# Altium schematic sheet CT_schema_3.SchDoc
size 400 x 230 mm
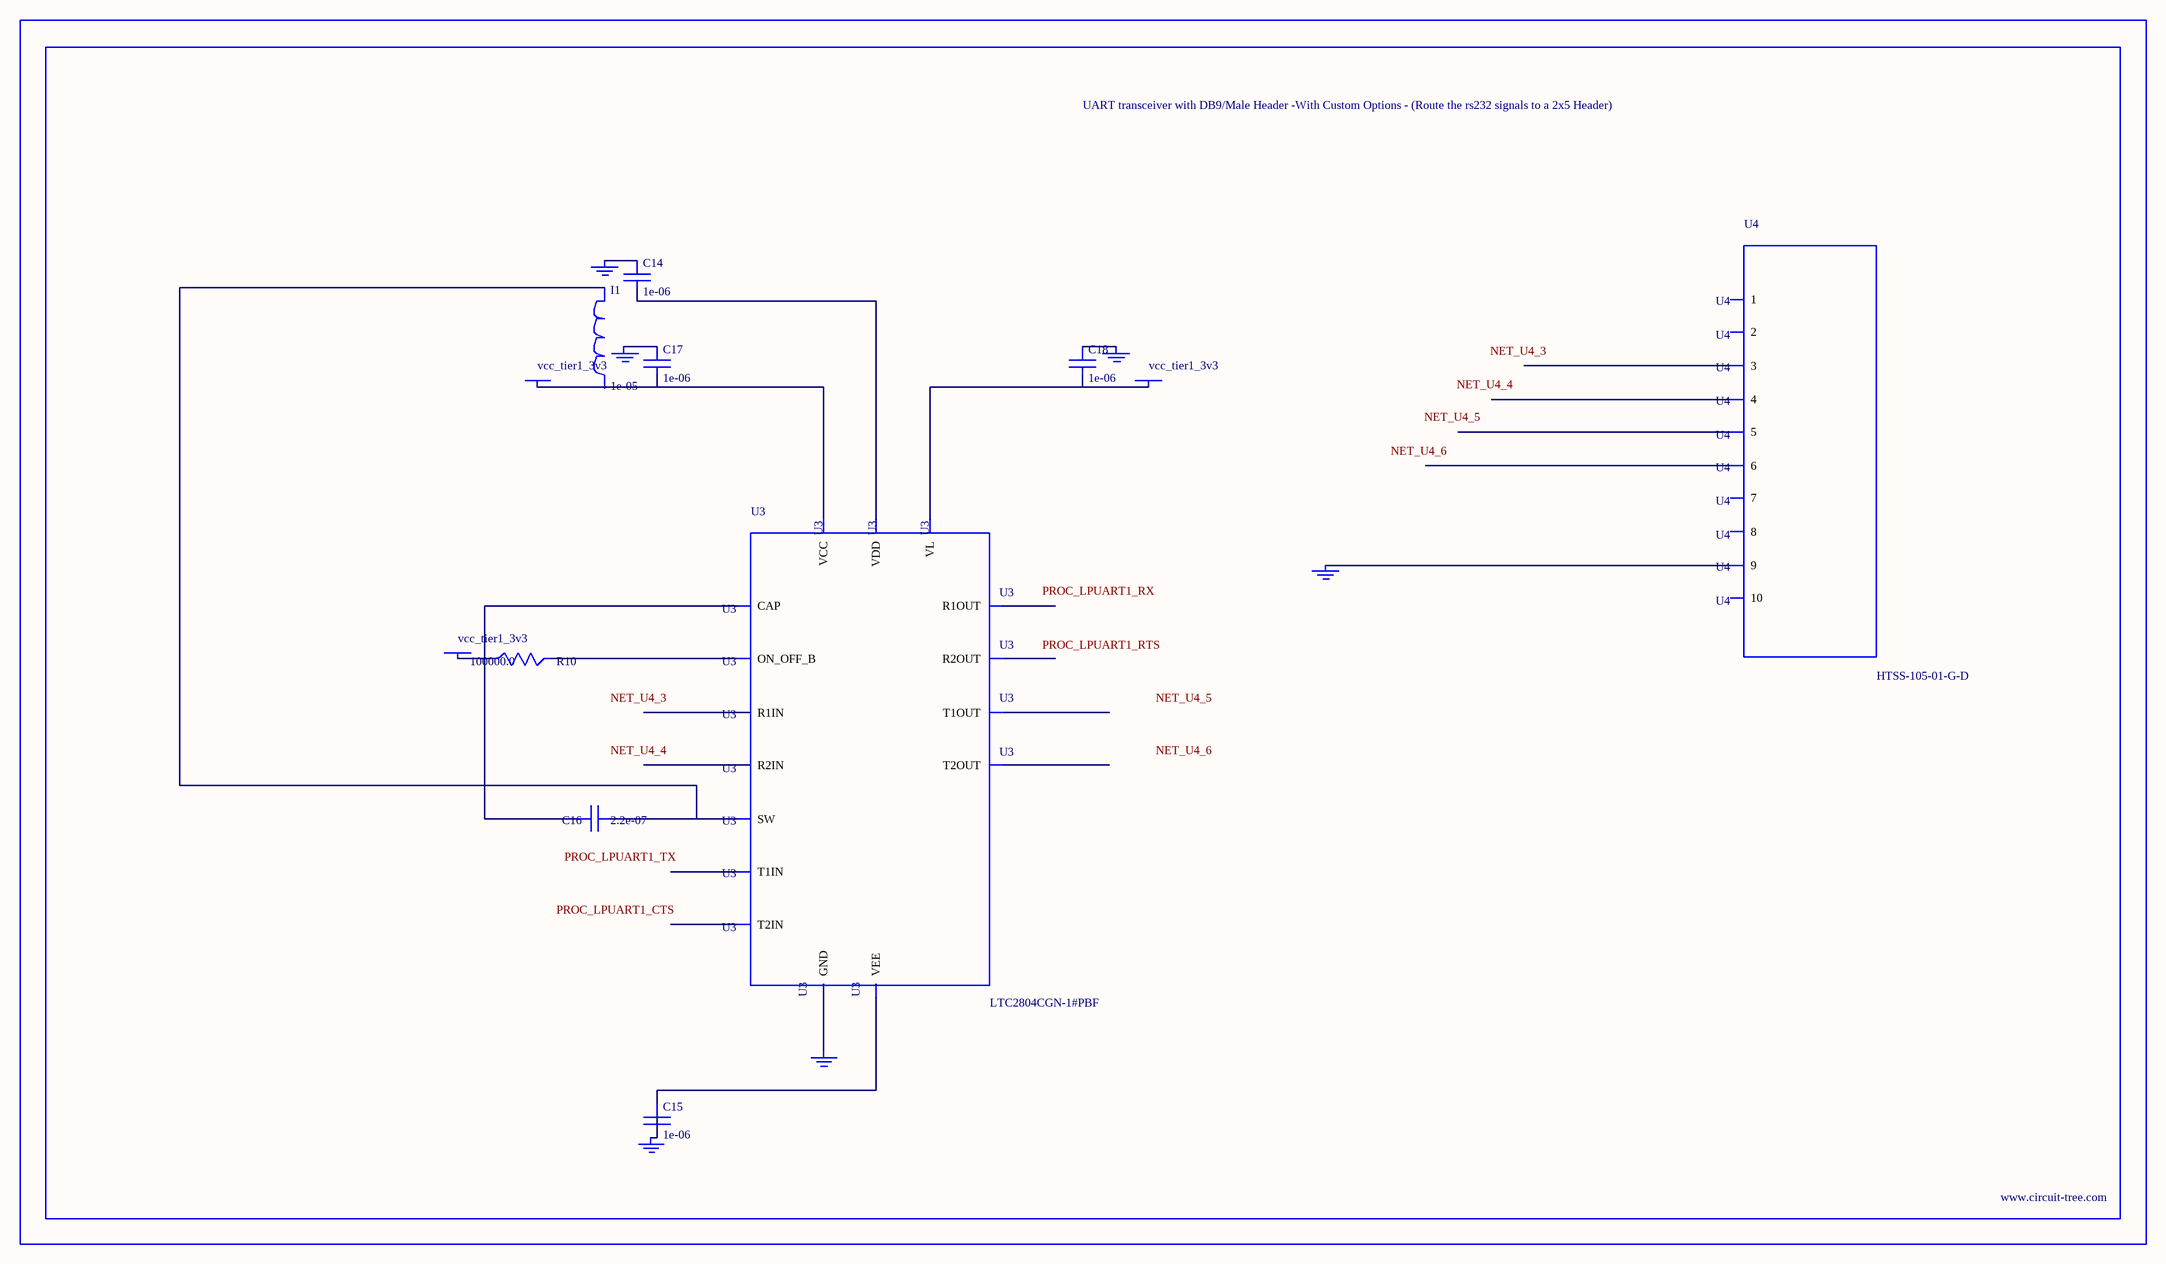
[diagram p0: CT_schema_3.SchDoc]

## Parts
BORDER2  (no value)
C14  1e-06  [C0603]
C15  1e-06  [C0603]
C16  2.2e-07  [C0603]
C17  1e-06  [C0603]
C18  1e-06  [C0603]
GND_INSTANCE_2_0  (no value)
GND_INSTANCE_2_1  (no value)
GND_INSTANCE_2_2  (no value)
GND_INSTANCE_2_3  (no value)
GND_INSTANCE_2_4  (no value)
GND_INSTANCE_2_5  (no value)
I1  1e-05  [L1210]
POWER_INSTANCE_2_0  vcc_tier1_3v3
POWER_INSTANCE_2_1  vcc_tier1_3v3
POWER_INSTANCE_2_2  vcc_tier1_3v3
R10  100000.0  [R0603]
U3  LTC2804CGN-1#PBF  [SSOP-16]
U4  HTSS-105-01-G-D  [HTSS-105-01-G-D]

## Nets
NetC14_1: C14.1 GND_INSTANCE_2_1.0(GND)
NetC14_2: C14.2 U3.6(VDD)
NetC15_1: C15.1 U3.9(VEE)
NetC15_2: C15.2 GND_INSTANCE_2_2.0(GND)
NetC16_1: C16.1 I1.1 U3.7(SW)
NetC16_2: C16.2 U3.10(CAP)
NetC17_1: C17.1 GND_INSTANCE_2_0.0(GND)
NetC17_2: C17.2 POWER_INSTANCE_2_0.0(PWR) U3.5(VCC)
NetC18_1: C18.1 GND_INSTANCE_2_3.0(GND)
NetC18_2: C18.2 POWER_INSTANCE_2_2.0(PWR) U3.12(VL)
NetGND_INSTANCE_2_4_0: GND_INSTANCE_2_4.0(GND) U3.8(GND)
NetGND_INSTANCE_2_5_0: GND_INSTANCE_2_5.0(GND) U4.9
NetPOWER_INSTANCE_2_1_0: POWER_INSTANCE_2_1.0(PWR) R10.1
NetR10_2: R10.2 U3.11(ON_OFF_B)

Not connected (* = marked no-connect by the designer): I1 2; U3 1(R1IN) 2(R2IN) 3(T1OUT) 4(T2OUT) 13(T2IN) 14(T1IN) 15(R2OUT) 16(R1OUT); U4 1 2 3 4 5 6 7 8 10

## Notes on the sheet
- Labels drawn without touching a wire or pin: NET_U4_3, NET_U4_4, NET_U4_5, NET_U4_6, PROC_LPUART1_CTS, PROC_LPUART1_RTS, PROC_LPUART1_RX, PROC_LPUART1_TX

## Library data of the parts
BORDER2 = BORDER_PAGE2
C14 C15 C17 C18 = C0603C105K3RACTU
C16 = C0603C224K3RAC
GND_INSTANCE_2_0-GND_INSTANCE_2_5 = GND
I1 = CBC3225T100MR
POWER_INSTANCE_2_0-POWER_INSTANCE_2_2 = PWR
R10 = RC0603JR-07100KL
